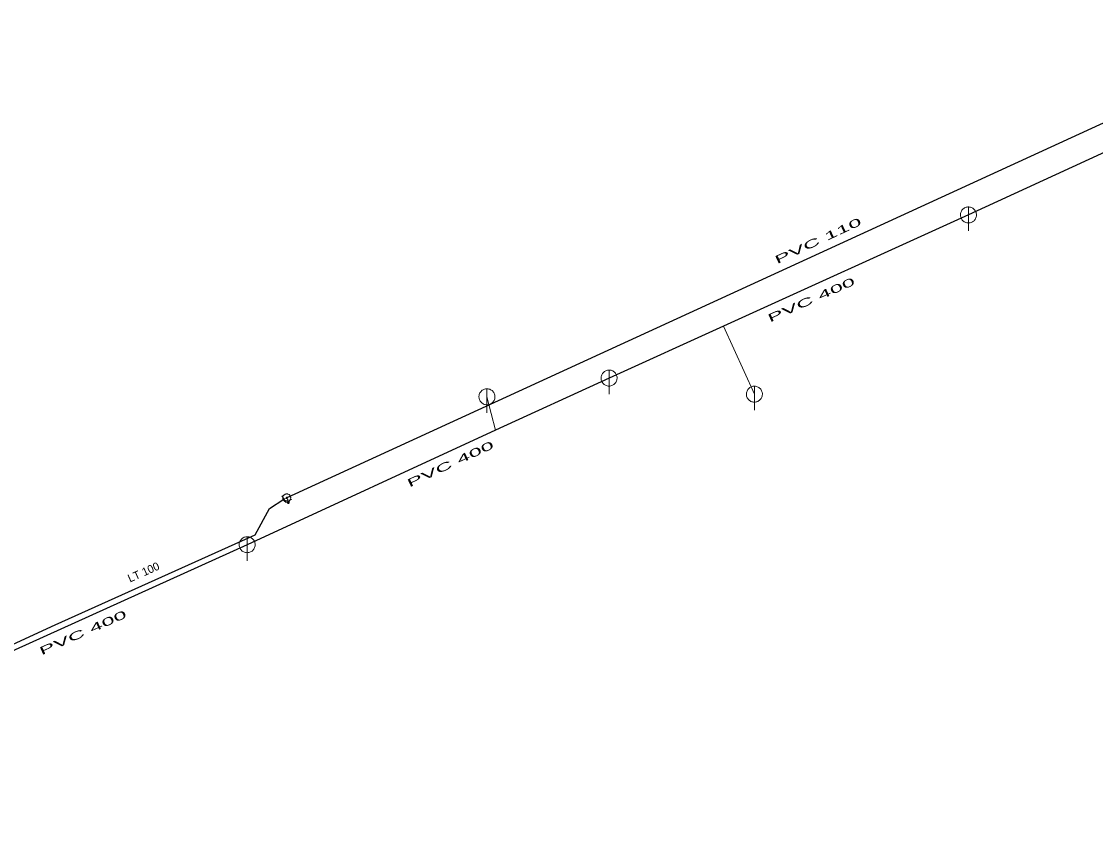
# Model space of a CAD drawing. Extents: x -659250 to -657316, y -997555 to -993684.
# Drawn here: x -657984.1 to -657849.9, y -996343.3 to -996242.1 of the extents above; entities that cross this region are included whole.
import ezdxf

# ---------------------------------------------------------------- set-up
doc = ezdxf.new("R2010")
doc.units = 0
doc.header["$LTSCALE"] = 0.4
doc.layers.add('1', color=7, linetype='Continuous')
for name, color, linetype, lineweight in [('11', 7, 'Continuous', 13), ('14', 7, 'Continuous', 25), ('17', 7, 'Continuous', 25), ('22', 7, 'Continuous', 13), ('34', 7, 'Continuous', 13), ('47', 7, 'Continuous', 13), ('9', 7, 'Continuous', 13)]:
    doc.layers.add(name, color=color, linetype=linetype, lineweight=lineweight)

msp = doc.modelspace()

# ---------------------------------------------------------------- linework, layer by layer
at = {"layer": '11'}
for p, q in [((-657892.48, -996288.68), (-657896.324, -996280.177)), ((-657925.899, -996289.01), (-657924.811, -996293.191))]:
    msp.add_line(p, q, dxfattribs=at)
at = {"layer": '14'}
msp.add_line((-657955.859, -996307.48), (-658002.53, -996328.629), dxfattribs=at)
for points in [[(-657823.5, -996246.87), (-657830.495, -996250.089), (-657865.73, -996266.3)], [(-657865.73, -996266.3), (-657896.324, -996280.177), (-657910.64, -996286.67)], [(-657910.64, -996286.67), (-657924.811, -996293.191), (-657955.859, -996307.48)]]:
    msp.add_lwpolyline(points, dxfattribs=at)
at = {"layer": '14', "lineweight": 13}
msp.add_lwpolyline([(-657951.27, -996301.8), (-657950.917, -996301.638), (-657950.765, -996301.92), (-657950.718, -996302.201)], dxfattribs=at)
at = {"layer": '17'}
msp.add_line((-657821.213, -996242.14), (-657950.917, -996301.638), dxfattribs=at)
msp.add_lwpolyline([(-658030.5, -996343.3), (-658027.489, -996341.48), (-658011.82, -996332.971), (-658002.858, -996328.082), (-657979.864, -996317.496), (-657954.87, -996306.27), (-657953.079, -996302.94), (-657951.27, -996301.8)], dxfattribs=at)
at = {"layer": '22'}
for p, q in [((-657865.73, -996268.3), (-657865.729, -996265.3)), ((-657910.64, -996288.67), (-657910.639, -996285.67)), ((-657892.48, -996290.68), (-657892.479, -996287.68)), ((-657925.899, -996291.01), (-657925.898, -996288.01)), ((-657955.859, -996309.48), (-657955.858, -996306.48))]:
    msp.add_line(p, q, dxfattribs=at)
for points in [[(-657864.73, -996266.3), (-657864.735, -996266.191), (-657864.753, -996266.083), (-657864.783, -996265.977), (-657864.823, -996265.876), (-657864.875, -996265.779), (-657864.937, -996265.689), (-657865.009, -996265.606), (-657865.089, -996265.532), (-657865.177, -996265.466), (-657865.271, -996265.411), (-657865.371, -996265.366), (-657865.476, -996265.333), (-657865.583, -996265.311), (-657865.692, -996265.301), (-657865.802, -996265.303), (-657865.91, -996265.317), (-657866.017, -996265.342), (-657866.12, -996265.379), (-657866.218, -996265.428), (-657866.31, -996265.486), (-657866.396, -996265.555), (-657866.473, -996265.632), (-657866.542, -996265.718), (-657866.601, -996265.81), (-657866.649, -996265.908), (-657866.686, -996266.011), (-657866.712, -996266.118), (-657866.726, -996266.226), (-657866.729, -996266.336), (-657866.719, -996266.445), (-657866.698, -996266.552), (-657866.664, -996266.656), (-657866.62, -996266.756), (-657866.565, -996266.851), (-657866.499, -996266.939), (-657866.425, -996267.019), (-657866.342, -996267.091), (-657866.252, -996267.153), (-657866.156, -996267.205), (-657866.054, -996267.246), (-657865.949, -996267.276), (-657865.841, -996267.294), (-657865.731, -996267.3), (-657865.622, -996267.294), (-657865.514, -996267.276), (-657865.409, -996267.247), (-657865.307, -996267.206), (-657865.21, -996267.154), (-657865.12, -996267.092), (-657865.037, -996267.021), (-657864.962, -996266.941), (-657864.897, -996266.853), (-657864.841, -996266.759), (-657864.797, -996266.659), (-657864.763, -996266.555), (-657864.741, -996266.447), (-657864.731, -996266.338)], [(-657909.64, -996286.67), (-657909.645, -996286.561), (-657909.663, -996286.453), (-657909.693, -996286.347), (-657909.733, -996286.246), (-657909.785, -996286.149), (-657909.847, -996286.059), (-657909.919, -996285.976), (-657909.999, -996285.902), (-657910.087, -996285.836), (-657910.181, -996285.781), (-657910.281, -996285.736), (-657910.386, -996285.703), (-657910.493, -996285.681), (-657910.602, -996285.671), (-657910.712, -996285.673), (-657910.82, -996285.687), (-657910.927, -996285.712), (-657911.03, -996285.749), (-657911.128, -996285.798), (-657911.22, -996285.856), (-657911.306, -996285.925), (-657911.383, -996286.002), (-657911.452, -996286.088), (-657911.511, -996286.18), (-657911.559, -996286.278), (-657911.596, -996286.381), (-657911.622, -996286.488), (-657911.636, -996286.596), (-657911.639, -996286.706), (-657911.629, -996286.815), (-657911.608, -996286.922), (-657911.574, -996287.026), (-657911.53, -996287.126), (-657911.475, -996287.221), (-657911.409, -996287.309), (-657911.335, -996287.389), (-657911.252, -996287.461), (-657911.162, -996287.523), (-657911.066, -996287.575), (-657910.964, -996287.616), (-657910.859, -996287.646), (-657910.751, -996287.664), (-657910.641, -996287.67), (-657910.532, -996287.664), (-657910.424, -996287.646), (-657910.319, -996287.617), (-657910.217, -996287.576), (-657910.12, -996287.524), (-657910.03, -996287.462), (-657909.947, -996287.391), (-657909.872, -996287.311), (-657909.807, -996287.223), (-657909.751, -996287.129), (-657909.707, -996287.029), (-657909.673, -996286.925), (-657909.651, -996286.817), (-657909.641, -996286.708)], [(-657891.48, -996288.68), (-657891.485, -996288.571), (-657891.503, -996288.463), (-657891.533, -996288.357), (-657891.573, -996288.256), (-657891.625, -996288.159), (-657891.687, -996288.069), (-657891.759, -996287.986), (-657891.839, -996287.912), (-657891.927, -996287.846), (-657892.021, -996287.791), (-657892.121, -996287.746), (-657892.226, -996287.713), (-657892.333, -996287.691), (-657892.442, -996287.681), (-657892.552, -996287.683), (-657892.66, -996287.697), (-657892.767, -996287.722), (-657892.87, -996287.759), (-657892.968, -996287.808), (-657893.06, -996287.866), (-657893.146, -996287.935), (-657893.223, -996288.012), (-657893.292, -996288.098), (-657893.351, -996288.19), (-657893.399, -996288.288), (-657893.436, -996288.391), (-657893.462, -996288.498), (-657893.476, -996288.606), (-657893.479, -996288.716), (-657893.469, -996288.825), (-657893.448, -996288.932), (-657893.414, -996289.036), (-657893.37, -996289.136), (-657893.315, -996289.231), (-657893.249, -996289.319), (-657893.175, -996289.399), (-657893.092, -996289.471), (-657893.002, -996289.533), (-657892.906, -996289.585), (-657892.804, -996289.626), (-657892.699, -996289.656), (-657892.591, -996289.674), (-657892.481, -996289.68), (-657892.372, -996289.674), (-657892.264, -996289.656), (-657892.159, -996289.627), (-657892.057, -996289.586), (-657891.96, -996289.534), (-657891.87, -996289.472), (-657891.787, -996289.401), (-657891.712, -996289.321), (-657891.647, -996289.233), (-657891.591, -996289.139), (-657891.547, -996289.039), (-657891.513, -996288.935), (-657891.491, -996288.827), (-657891.481, -996288.718)], [(-657924.899, -996289.01), (-657924.904, -996288.901), (-657924.922, -996288.793), (-657924.952, -996288.687), (-657924.992, -996288.586), (-657925.044, -996288.489), (-657925.106, -996288.399), (-657925.178, -996288.316), (-657925.258, -996288.242), (-657925.346, -996288.176), (-657925.44, -996288.121), (-657925.54, -996288.076), (-657925.645, -996288.043), (-657925.752, -996288.021), (-657925.861, -996288.011), (-657925.971, -996288.013), (-657926.079, -996288.027), (-657926.186, -996288.052), (-657926.289, -996288.089), (-657926.387, -996288.138), (-657926.479, -996288.196), (-657926.565, -996288.265), (-657926.642, -996288.342), (-657926.711, -996288.428), (-657926.77, -996288.52), (-657926.818, -996288.618), (-657926.855, -996288.721), (-657926.881, -996288.828), (-657926.895, -996288.936), (-657926.898, -996289.046), (-657926.888, -996289.155), (-657926.867, -996289.262), (-657926.833, -996289.366), (-657926.789, -996289.466), (-657926.734, -996289.561), (-657926.668, -996289.649), (-657926.594, -996289.729), (-657926.511, -996289.801), (-657926.421, -996289.863), (-657926.325, -996289.915), (-657926.223, -996289.956), (-657926.118, -996289.986), (-657926.01, -996290.004), (-657925.9, -996290.01), (-657925.791, -996290.004), (-657925.683, -996289.986), (-657925.578, -996289.957), (-657925.476, -996289.916), (-657925.379, -996289.864), (-657925.289, -996289.802), (-657925.206, -996289.731), (-657925.131, -996289.651), (-657925.066, -996289.563), (-657925.01, -996289.469), (-657924.966, -996289.369), (-657924.932, -996289.265), (-657924.91, -996289.157), (-657924.9, -996289.048)], [(-657954.859, -996307.48), (-657954.864, -996307.371), (-657954.882, -996307.263), (-657954.912, -996307.157), (-657954.952, -996307.056), (-657955.004, -996306.959), (-657955.066, -996306.869), (-657955.138, -996306.786), (-657955.218, -996306.712), (-657955.306, -996306.646), (-657955.4, -996306.591), (-657955.5, -996306.546), (-657955.605, -996306.513), (-657955.712, -996306.491), (-657955.821, -996306.481), (-657955.931, -996306.483), (-657956.039, -996306.497), (-657956.146, -996306.522), (-657956.249, -996306.559), (-657956.347, -996306.608), (-657956.439, -996306.666), (-657956.525, -996306.735), (-657956.602, -996306.812), (-657956.671, -996306.898), (-657956.73, -996306.99), (-657956.778, -996307.088), (-657956.815, -996307.191), (-657956.841, -996307.298), (-657956.855, -996307.406), (-657956.858, -996307.516), (-657956.848, -996307.625), (-657956.827, -996307.732), (-657956.793, -996307.836), (-657956.749, -996307.936), (-657956.694, -996308.031), (-657956.628, -996308.119), (-657956.554, -996308.199), (-657956.471, -996308.271), (-657956.381, -996308.333), (-657956.285, -996308.385), (-657956.183, -996308.426), (-657956.078, -996308.456), (-657955.97, -996308.474), (-657955.86, -996308.48), (-657955.751, -996308.474), (-657955.643, -996308.456), (-657955.538, -996308.427), (-657955.436, -996308.386), (-657955.339, -996308.334), (-657955.249, -996308.272), (-657955.166, -996308.201), (-657955.091, -996308.121), (-657955.026, -996308.033), (-657954.97, -996307.939), (-657954.926, -996307.839), (-657954.892, -996307.735), (-657954.87, -996307.627), (-657954.86, -996307.518)]]:
    msp.add_lwpolyline(points, close=True, dxfattribs=at)
at = {"layer": '34'}
for p, q in [((-657951.536, -996301.377), (-657951.003, -996302.223)), ((-657950.271, -996301.838), (-657951.258, -996302))]:
    msp.add_line(p, q, dxfattribs=at)
at = {"layer": '47'}
for points in [[(-657951.371, -996301.846), (-657951.347, -996301.892), (-657951.318, -996301.936), (-657951.284, -996301.976), (-657951.247, -996302.013), (-657951.206, -996302.045), (-657951.161, -996302.073), (-657951.114, -996302.096), (-657951.065, -996302.114), (-657951.015, -996302.127), (-657950.963, -996302.135), (-657950.91, -996302.138), (-657950.858, -996302.133), (-657950.807, -996302.125), (-657950.757, -996302.111), (-657950.708, -996302.092), (-657950.662, -996302.068), (-657950.618, -996302.039), (-657950.578, -996302.005), (-657950.541, -996301.968), (-657950.509, -996301.927), (-657950.481, -996301.882), (-657950.457, -996301.835), (-657950.439, -996301.786), (-657950.426, -996301.736), (-657950.419, -996301.684), (-657950.416, -996301.631), (-657950.42, -996301.579), (-657950.429, -996301.528), (-657950.443, -996301.478), (-657950.462, -996301.429), (-657950.486, -996301.383), (-657950.515, -996301.339), (-657950.548, -996301.298), (-657950.586, -996301.262), (-657950.627, -996301.23), (-657950.671, -996301.201), (-657950.718, -996301.178), (-657950.767, -996301.16), (-657950.818, -996301.147), (-657950.87, -996301.14), (-657950.923, -996301.137), (-657950.974, -996301.14), (-657951.026, -996301.15), (-657951.076, -996301.164), (-657951.125, -996301.183), (-657951.171, -996301.207), (-657951.215, -996301.236), (-657951.255, -996301.269), (-657951.292, -996301.307), (-657951.324, -996301.348), (-657951.353, -996301.392), (-657951.375, -996301.439), (-657951.393, -996301.488), (-657951.406, -996301.539), (-657951.414, -996301.591), (-657951.417, -996301.644), (-657951.413, -996301.695), (-657951.404, -996301.747), (-657951.39, -996301.797)], [(-657950.991, -996301.672), (-657950.987, -996301.68), (-657950.982, -996301.686), (-657950.977, -996301.693), (-657950.971, -996301.699), (-657950.964, -996301.704), (-657950.956, -996301.709), (-657950.949, -996301.713), (-657950.941, -996301.716), (-657950.933, -996301.718), (-657950.924, -996301.719), (-657950.915, -996301.719), (-657950.907, -996301.719), (-657950.899, -996301.717), (-657950.89, -996301.716), (-657950.882, -996301.712), (-657950.874, -996301.708), (-657950.868, -996301.703), (-657950.861, -996301.698), (-657950.855, -996301.692), (-657950.85, -996301.685), (-657950.845, -996301.677), (-657950.841, -996301.67), (-657950.838, -996301.662), (-657950.836, -996301.653), (-657950.835, -996301.645), (-657950.835, -996301.636), (-657950.835, -996301.628), (-657950.837, -996301.62), (-657950.838, -996301.611), (-657950.842, -996301.603), (-657950.846, -996301.595), (-657950.851, -996301.589), (-657950.856, -996301.582), (-657950.862, -996301.576), (-657950.869, -996301.571), (-657950.876, -996301.566), (-657950.884, -996301.562), (-657950.892, -996301.559), (-657950.901, -996301.557), (-657950.909, -996301.556), (-657950.918, -996301.556), (-657950.926, -996301.556), (-657950.934, -996301.558), (-657950.943, -996301.559), (-657950.951, -996301.563), (-657950.959, -996301.567), (-657950.965, -996301.572), (-657950.972, -996301.577), (-657950.978, -996301.583), (-657950.983, -996301.59), (-657950.988, -996301.597), (-657950.992, -996301.605), (-657950.995, -996301.613), (-657950.997, -996301.621), (-657950.998, -996301.63), (-657950.998, -996301.639), (-657950.998, -996301.647), (-657950.996, -996301.655), (-657950.995, -996301.664)]]:
    msp.add_lwpolyline(points, close=True, dxfattribs=at)
at = {"layer": '9'}
for points in [[(-657950.844, -996302.201), (-657950.844, -996302.214), (-657950.842, -996302.227), (-657950.839, -996302.24), (-657950.834, -996302.252), (-657950.828, -996302.264), (-657950.821, -996302.275), (-657950.813, -996302.285), (-657950.803, -996302.295), (-657950.793, -996302.303), (-657950.782, -996302.31), (-657950.77, -996302.316), (-657950.758, -996302.321), (-657950.745, -996302.324), (-657950.732, -996302.326), (-657950.719, -996302.328), (-657950.706, -996302.327), (-657950.693, -996302.325), (-657950.68, -996302.322), (-657950.668, -996302.317), (-657950.656, -996302.311), (-657950.645, -996302.304), (-657950.635, -996302.296), (-657950.625, -996302.286), (-657950.617, -996302.276), (-657950.61, -996302.265), (-657950.604, -996302.253), (-657950.599, -996302.241), (-657950.596, -996302.228), (-657950.594, -996302.215), (-657950.592, -996302.202), (-657950.593, -996302.189), (-657950.595, -996302.176), (-657950.598, -996302.163), (-657950.603, -996302.151), (-657950.608, -996302.139), (-657950.616, -996302.128), (-657950.624, -996302.118), (-657950.634, -996302.108), (-657950.644, -996302.1), (-657950.655, -996302.093), (-657950.667, -996302.087), (-657950.679, -996302.082), (-657950.692, -996302.079), (-657950.705, -996302.077), (-657950.718, -996302.076), (-657950.731, -996302.076), (-657950.744, -996302.078), (-657950.757, -996302.081), (-657950.769, -996302.086), (-657950.781, -996302.092), (-657950.792, -996302.099), (-657950.802, -996302.107), (-657950.812, -996302.117), (-657950.82, -996302.127), (-657950.827, -996302.138), (-657950.833, -996302.15), (-657950.838, -996302.162), (-657950.841, -996302.175), (-657950.843, -996302.188)], [(-657950.824, -996302.201), (-657950.825, -996302.212), (-657950.823, -996302.223), (-657950.82, -996302.234), (-657950.816, -996302.244), (-657950.811, -996302.254), (-657950.805, -996302.263), (-657950.798, -996302.272), (-657950.79, -996302.28), (-657950.781, -996302.287), (-657950.772, -996302.293), (-657950.762, -996302.298), (-657950.752, -996302.302), (-657950.741, -996302.305), (-657950.73, -996302.308), (-657950.719, -996302.308), (-657950.708, -996302.308), (-657950.697, -996302.306), (-657950.686, -996302.303), (-657950.676, -996302.299), (-657950.666, -996302.294), (-657950.657, -996302.288), (-657950.648, -996302.281), (-657950.64, -996302.273), (-657950.633, -996302.264), (-657950.627, -996302.255), (-657950.622, -996302.245), (-657950.618, -996302.235), (-657950.615, -996302.224), (-657950.613, -996302.213), (-657950.612, -996302.202), (-657950.612, -996302.191), (-657950.614, -996302.18), (-657950.617, -996302.169), (-657950.621, -996302.159), (-657950.626, -996302.149), (-657950.632, -996302.14), (-657950.639, -996302.131), (-657950.647, -996302.123), (-657950.656, -996302.116), (-657950.665, -996302.11), (-657950.675, -996302.105), (-657950.684, -996302.101), (-657950.696, -996302.098), (-657950.706, -996302.096), (-657950.718, -996302.096), (-657950.729, -996302.095), (-657950.74, -996302.097), (-657950.751, -996302.1), (-657950.761, -996302.104), (-657950.771, -996302.109), (-657950.78, -996302.115), (-657950.789, -996302.122), (-657950.797, -996302.13), (-657950.804, -996302.139), (-657950.809, -996302.148), (-657950.815, -996302.158), (-657950.819, -996302.168), (-657950.822, -996302.179), (-657950.824, -996302.19)], [(-657950.805, -996302.201), (-657950.805, -996302.21), (-657950.804, -996302.219), (-657950.801, -996302.228), (-657950.798, -996302.236), (-657950.794, -996302.244), (-657950.789, -996302.252), (-657950.782, -996302.259), (-657950.777, -996302.265), (-657950.77, -996302.271), (-657950.762, -996302.276), (-657950.754, -996302.28), (-657950.746, -996302.283), (-657950.737, -996302.286), (-657950.728, -996302.287), (-657950.719, -996302.289), (-657950.71, -996302.288), (-657950.701, -996302.287), (-657950.692, -996302.284), (-657950.684, -996302.281), (-657950.676, -996302.277), (-657950.668, -996302.272), (-657950.661, -996302.266), (-657950.655, -996302.26), (-657950.649, -996302.253), (-657950.644, -996302.245), (-657950.64, -996302.237), (-657950.637, -996302.229), (-657950.634, -996302.22), (-657950.633, -996302.211), (-657950.63, -996302.202), (-657950.632, -996302.193), (-657950.633, -996302.184), (-657950.636, -996302.175), (-657950.639, -996302.167), (-657950.643, -996302.159), (-657950.648, -996302.151), (-657950.654, -996302.144), (-657950.66, -996302.138), (-657950.667, -996302.132), (-657950.675, -996302.127), (-657950.683, -996302.123), (-657950.691, -996302.12), (-657950.7, -996302.117), (-657950.709, -996302.116), (-657950.718, -996302.115), (-657950.727, -996302.115), (-657950.736, -996302.116), (-657950.745, -996302.119), (-657950.753, -996302.122), (-657950.761, -996302.126), (-657950.769, -996302.131), (-657950.776, -996302.137), (-657950.782, -996302.143), (-657950.788, -996302.15), (-657950.793, -996302.158), (-657950.797, -996302.166), (-657950.8, -996302.174), (-657950.803, -996302.183), (-657950.804, -996302.192)], [(-657950.785, -996302.201), (-657950.785, -996302.208), (-657950.784, -996302.215), (-657950.782, -996302.222), (-657950.78, -996302.228), (-657950.777, -996302.234), (-657950.773, -996302.24), (-657950.769, -996302.246), (-657950.764, -996302.251), (-657950.758, -996302.255), (-657950.752, -996302.259), (-657950.746, -996302.262), (-657950.74, -996302.265), (-657950.733, -996302.266), (-657950.726, -996302.269), (-657950.719, -996302.269), (-657950.712, -996302.269), (-657950.705, -996302.267), (-657950.698, -996302.266), (-657950.692, -996302.263), (-657950.684, -996302.26), (-657950.68, -996302.256), (-657950.674, -996302.252), (-657950.669, -996302.247), (-657950.665, -996302.241), (-657950.661, -996302.235), (-657950.657, -996302.229), (-657950.655, -996302.223), (-657950.653, -996302.216), (-657950.652, -996302.209), (-657950.651, -996302.202), (-657950.651, -996302.195), (-657950.652, -996302.188), (-657950.654, -996302.181), (-657950.657, -996302.175), (-657950.66, -996302.168), (-657950.664, -996302.163), (-657950.668, -996302.157), (-657950.673, -996302.152), (-657950.679, -996302.148), (-657950.684, -996302.144), (-657950.691, -996302.141), (-657950.697, -996302.138), (-657950.704, -996302.136), (-657950.711, -996302.135), (-657950.718, -996302.135), (-657950.725, -996302.135), (-657950.732, -996302.135), (-657950.739, -996302.137), (-657950.745, -996302.14), (-657950.751, -996302.143), (-657950.757, -996302.147), (-657950.763, -996302.151), (-657950.768, -996302.156), (-657950.772, -996302.162), (-657950.776, -996302.167), (-657950.779, -996302.174), (-657950.782, -996302.18), (-657950.782, -996302.187), (-657950.785, -996302.194)], [(-657950.765, -996302.201), (-657950.765, -996302.206), (-657950.765, -996302.211), (-657950.764, -996302.216), (-657950.762, -996302.22), (-657950.76, -996302.225), (-657950.757, -996302.229), (-657950.754, -996302.232), (-657950.75, -996302.236), (-657950.747, -996302.239), (-657950.743, -996302.242), (-657950.738, -996302.244), (-657950.733, -996302.246), (-657950.729, -996302.247), (-657950.724, -996302.249), (-657950.719, -996302.249), (-657950.714, -996302.249), (-657950.709, -996302.248), (-657950.704, -996302.247), (-657950.7, -996302.245), (-657950.695, -996302.243), (-657950.691, -996302.24), (-657950.687, -996302.237), (-657950.684, -996302.233), (-657950.681, -996302.23), (-657950.678, -996302.226), (-657950.676, -996302.221), (-657950.674, -996302.217), (-657950.673, -996302.212), (-657950.672, -996302.207), (-657950.671, -996302.202), (-657950.671, -996302.197), (-657950.672, -996302.192), (-657950.673, -996302.187), (-657950.675, -996302.183), (-657950.677, -996302.178), (-657950.68, -996302.174), (-657950.683, -996302.17), (-657950.686, -996302.167), (-657950.69, -996302.164), (-657950.694, -996302.161), (-657950.699, -996302.159), (-657950.703, -996302.157), (-657950.708, -996302.156), (-657950.713, -996302.155), (-657950.718, -996302.155), (-657950.723, -996302.155), (-657950.728, -996302.156), (-657950.733, -996302.156), (-657950.737, -996302.158), (-657950.742, -996302.16), (-657950.746, -996302.163), (-657950.749, -996302.166), (-657950.753, -996302.169), (-657950.755, -996302.173), (-657950.759, -996302.177), (-657950.761, -996302.182), (-657950.763, -996302.186), (-657950.764, -996302.191), (-657950.765, -996302.196)], [(-657950.745, -996302.201), (-657950.745, -996302.204), (-657950.746, -996302.207), (-657950.745, -996302.209), (-657950.744, -996302.212), (-657950.743, -996302.215), (-657950.741, -996302.217), (-657950.739, -996302.219), (-657950.737, -996302.221), (-657950.735, -996302.223), (-657950.733, -996302.225), (-657950.73, -996302.227), (-657950.727, -996302.228), (-657950.725, -996302.228), (-657950.722, -996302.229), (-657950.719, -996302.229), (-657950.716, -996302.229), (-657950.713, -996302.229), (-657950.71, -996302.228), (-657950.708, -996302.227), (-657950.705, -996302.226), (-657950.703, -996302.224), (-657950.7, -996302.222), (-657950.698, -996302.22), (-657950.697, -996302.218), (-657950.695, -996302.216), (-657950.694, -996302.213), (-657950.692, -996302.21), (-657950.692, -996302.208), (-657950.691, -996302.205), (-657950.69, -996302.202), (-657950.691, -996302.199), (-657950.691, -996302.196), (-657950.692, -996302.193), (-657950.693, -996302.191), (-657950.694, -996302.188), (-657950.696, -996302.186), (-657950.697, -996302.183), (-657950.699, -996302.181), (-657950.702, -996302.18), (-657950.704, -996302.178), (-657950.706, -996302.177), (-657950.709, -996302.176), (-657950.712, -996302.175), (-657950.715, -996302.175), (-657950.718, -996302.174), (-657950.721, -996302.175), (-657950.724, -996302.174), (-657950.726, -996302.176), (-657950.729, -996302.176), (-657950.732, -996302.177), (-657950.733, -996302.179), (-657950.736, -996302.18), (-657950.738, -996302.182), (-657950.74, -996302.185), (-657950.742, -996302.187), (-657950.743, -996302.19), (-657950.744, -996302.192), (-657950.745, -996302.195), (-657950.745, -996302.198)], [(-657950.726, -996302.201), (-657950.726, -996302.203), (-657950.726, -996302.203), (-657950.725, -996302.203), (-657950.725, -996302.205), (-657950.726, -996302.206), (-657950.724, -996302.206), (-657950.724, -996302.206), (-657950.724, -996302.208), (-657950.724, -996302.208), (-657950.723, -996302.209), (-657950.721, -996302.209), (-657950.721, -996302.209), (-657950.721, -996302.21), (-657950.719, -996302.21), (-657950.719, -996302.21), (-657950.718, -996302.21), (-657950.717, -996302.21), (-657950.717, -996302.209), (-657950.716, -996302.209), (-657950.714, -996302.209), (-657950.714, -996302.208), (-657950.714, -996302.208), (-657950.713, -996302.207), (-657950.713, -996302.207), (-657950.711, -996302.206), (-657950.711, -996302.205), (-657950.71, -996302.204), (-657950.71, -996302.204), (-657950.71, -996302.203), (-657950.71, -996302.202), (-657950.71, -996302.201), (-657950.71, -996302.2), (-657950.71, -996302.2), (-657950.711, -996302.199), (-657950.711, -996302.198), (-657950.712, -996302.197), (-657950.712, -996302.197), (-657950.713, -996302.196), (-657950.713, -996302.196), (-657950.714, -996302.195), (-657950.715, -996302.195), (-657950.716, -996302.194), (-657950.716, -996302.194), (-657950.717, -996302.194), (-657950.718, -996302.194), (-657950.719, -996302.194), (-657950.72, -996302.194), (-657950.72, -996302.194), (-657950.721, -996302.195), (-657950.722, -996302.194), (-657950.723, -996302.196), (-657950.723, -996302.196), (-657950.724, -996302.196), (-657950.724, -996302.196), (-657950.725, -996302.198), (-657950.725, -996302.199), (-657950.725, -996302.2), (-657950.726, -996302.2), (-657950.726, -996302.201)]]:
    msp.add_lwpolyline(points, close=True, dxfattribs=at)

# ---------------------------------------------------------------- texts
at = {"layer": '1', "width": 2.2}
for s, rotation, p in [('PVC 110 ', 25, (-657889.656, -996272.452)), ('PVC 400 ', 24, (-657890.551, -996279.738)), ('PVC 400 ', 25, (-657935.599, -996300.341)), ('PVC 400 ', 24, (-657981.562, -996321.307))]:
    msp.add_text(s, height=1, rotation=rotation, dxfattribs=at).set_placement(p)
at = {"layer": '1'}
msp.add_text('LT 100', height=1, rotation=24, dxfattribs=at).set_placement((-657970.507, -996312.213))

doc.saveas('drawing.dxf')
